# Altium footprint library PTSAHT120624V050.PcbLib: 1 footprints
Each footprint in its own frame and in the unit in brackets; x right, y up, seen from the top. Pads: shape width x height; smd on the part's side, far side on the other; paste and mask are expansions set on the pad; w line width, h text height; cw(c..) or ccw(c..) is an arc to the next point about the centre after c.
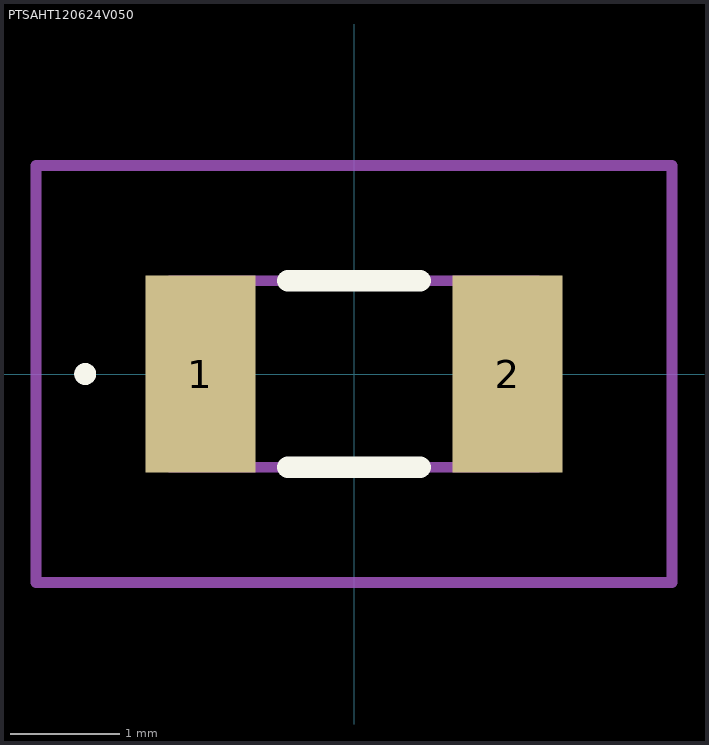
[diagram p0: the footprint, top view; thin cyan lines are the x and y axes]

## PTSAHT120624V050 [mm]
pads (2):
  rect 1x1.8 smd: 1(-1.4,0) 2(1.4,0)
Top Overlay:
  lines w0.1: -2.5,0 -2.5,0 ; -2.5,0 ccw(c-2.45,0) -2.4,0 ; -2.5,0 cw(c-2.45,0) -2.4,0 ; -2.4,0 -2.4,0
  lines w0.2: -0.6,-0.85 0.6,-0.85 ; -0.6,0.85 0.6,0.85
Mechanical 15:
  lines w0.1: -1.675,-0.85 1.675,-0.85 1.675,0.85 -1.675,0.85 -1.675,-0.85
Mechanical 20:
  lines w0.1: -2.9,-1.9 2.9,-1.9 2.9,1.9 -2.9,1.9 -2.9,-1.9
